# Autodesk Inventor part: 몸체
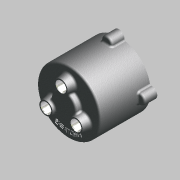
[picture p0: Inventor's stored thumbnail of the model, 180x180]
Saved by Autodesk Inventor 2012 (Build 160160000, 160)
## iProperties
Company: 한국ATC센터
Created: 2014-07
Part Number: 몸체
Document SubType Name: 모델링
Designer: KYOUNG IL JANG
Material: 알루미늄-6061
Mass: 475.555 g
Surface Area: 687.662 cm^2
Volume: 175.481 cm^3
Density: 2.71 g/cm^3
변환 표준: STEP AP214IS
파일 이름: C:\Users\SeoGD\Desktop\?쒗뿕\紐몄껜.stp
전처리기: Build: 253, Release: 2010 SP1 - Date: Wed 07/29/2009
전송 단위: 밀리미터
불확실성: 0.01
Author: KYOUNG IL JANG
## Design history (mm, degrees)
sketch "스케치2"
  geometry: C1 r 50 at (0, 0); 1 further point
  constraints: 1 centre point, 1 coincident
  dimensions: "d9" = 100 diameter of C1
extrude "돌출2" new body sketch "스케치2" distance "d10" = 80; taper "d11" = 0 deg
feature "쉘1" dims "d12" = 5
sketch "스케치3" dims "d13" = 55
  geometry: C1 r 7.5 at (0, 27.5); C2 r 12.5 at (0, 27.5); 2 further points
  constraints: 2 centre point, 2 coincident, 2 vertical alignment, 2 other
  dimensions: "d14" = 15 diameter of C1; "d15" = 25 diameter of C2
extrude "돌출3" join sketch "스케치3" distance "d16" = 12; taper "d17" = -10 deg
hole "구멍2" diameter "d20" = 15; stored, may be unused: countersink angle "d24" = 90 deg, drill point angle "d26" = 118 deg; dims "d18" = 10, "d19" = 10, "d21" = 6, "d22" = 4, "d23" = 2, "d25" = 15
chamfer "모따기1" distance "d27" = 1; stored, may be unused: second distance "d28" = 2, angle "d29" = 45 deg
sketch "스케치4"
  geometry: L1 (0, 0)-(0, 88); L2 (0, 70)-(13.16, 70); L3 (-45, 75)-(45, 75) reference; L4 (-50, 80)-(50, 80) reference; L5 (13.16, 70)-(14.5, 75); L6 (20, 80)-(20, 88); L7 (20, 88)-(0, 88); L8 (20, 80)-(14.5, 75)
  constraints: 12 end point, 3 point on line, 2 perpendicular, 1 vertical
  dimensions: "d34" = 40 diameter of L6 L1; "d35" = 105 deg angle of L5 L3; "d36" = 5 distance between parallel lines of L2 L3; "d37" = 8 distance between parallel lines of L7 L4; "d51" = 29 diameter of L5.end L1
revolve "회전1" sketch "스케치4" stored, may be unused: angle "d38" = 90 deg
hole "구멍3" diameter "d41" = 15; stored, may be unused: countersink angle "d45" = 90 deg, drill point angle "d47" = 0 deg; dims "d39" = 10, "d40" = 10, "d42" = 6, "d43" = 22, "d44" = 13, "d46" = 15
chamfer "모따기2" distance "d48" = 1; stored, may be unused: second distance "d49" = 2, angle "d50" = 45 deg
fillet "모깎기1" dims "d52" = 3
fillet "모깎기2" dims "d53" = 3, "d72" = 0.2
sketch "스케치5"
  geometry: A1 r 50 centre (0, 0) between (50, 0) and (-8.074, 49.344) reference; A2 r 8.5 centre (0, 52) between (8.074, 49.344) and (-8.074, 49.344); 1 further point
  constraints: 5 point on circle, 1 centre point, 1 horizontal alignment
  dimensions: "d54" = 90 deg dimension on point (0, 0) A2.centre A1.start; "d55" = 52 distance of A2.centre point (0, 0); "d56" = 17 diameter of A2
extrude "돌출4" join sketch "스케치5" distance "d57" = 20; taper "d58" = 0 deg
fillet "모깎기3" dims "d59" = 3
hole "구멍4" diameter "d62" = 4.134; stored, may be unused: countersink angle "d66" = 90 deg, drill point angle "d68" = 118 deg; dims "d60" = 10, "d61" = 10, "d63" = 12, "d64" = 22, "d65" = 13, "d67" = 15
sketch "스케치6"
  geometry: C1 r 47 at (0, 0) reference; C2 r 42.5 at (0, 0); 1 further point
  constraints: 1 centre point, 1 coincident, 1 other
  dimensions: "d73" = 85 diameter of C2
feature "엠보싱1" sketch "스케치6" dims "d74" = 1, "d75" = 0
node "솔리드1"
node "솔리드 본체"
node "곡면 본체"
pattern_circular "원형 패턴1" dims "d31" = 360 deg
pattern_circular "원형 패턴2" dims "d70" = 360 deg
node "솔리드2"
